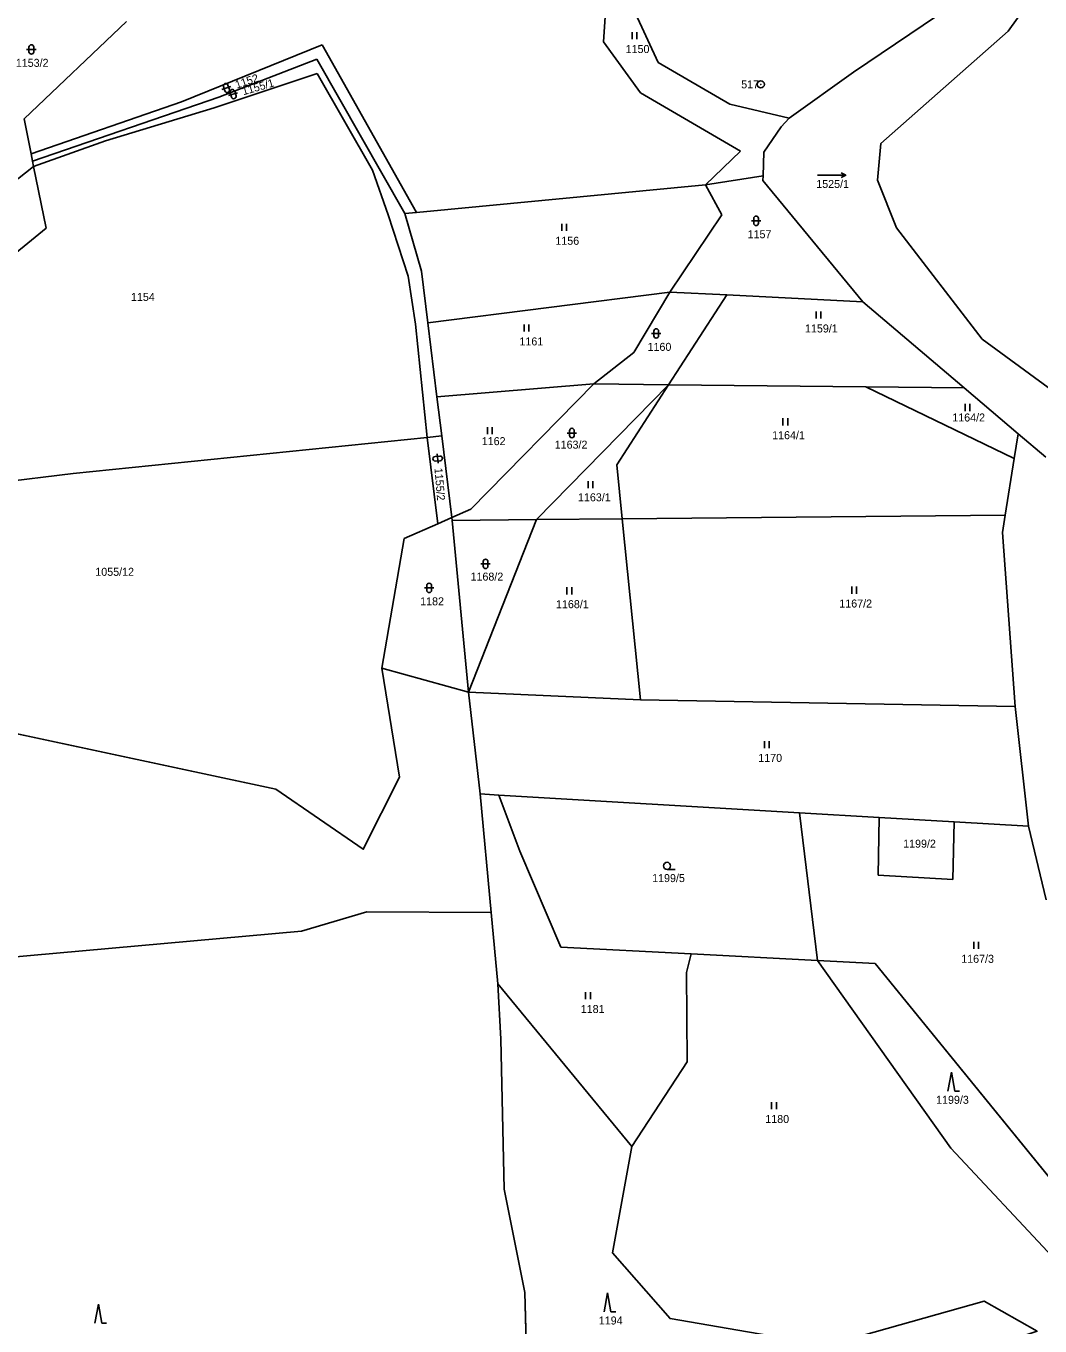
# Model space of a CAD drawing. Extents: x -760642 to -757221, y -1092371 to -1088855.
# Drawn here: x -759256.9 to -759041.5, y -1090879.2 to -1090603 of the extents above; entities that cross this region are included whole.
import ezdxf

# ---------------------------------------------------------------- set-up
doc = ezdxf.new("R2010")
doc.units = 0
for name, color, linetype in [('Vrstva 1', 7, 'Continuous'), ('Vrstva 17', 7, 'Continuous'), ('Vrstva 18', 7, 'Continuous'), ('Vrstva 24', 7, 'Continuous'), ('Vrstva 25', 7, 'Continuous'), ('Vrstva 30', 7, 'Continuous')]:
    doc.layers.add(name, color=color, linetype=linetype)

msp = doc.modelspace()

# ---------------------------------------------------------------- linework, layer by layer
at = {"layer": 'Vrstva 1'}
for p, q in [((-759132.43, -1090577.06), (-759134.2, -1090606.39)), ((-759033.66, -1090583.79), (-759048.27, -1090604.13)), ((-759127.44, -1090600.38), (-759122.61, -1090610.8)), ((-759063.28, -1090600.8), (-759081.11, -1090612.81)), ((-759235.58, -1090602.05), (-759257.35, -1090622.75)), ((-759048.27, -1090604.13), (-759075.3, -1090628.01)), ((-759134.2, -1090606.39), (-759126.37, -1090617.23)), ((-759223.9, -1090619.16), (-759194, -1090607.04)), ((-759194, -1090607.04), (-759173.99, -1090642.62)), ((-759195.13, -1090610.05), (-759215.93, -1090618.11)), ((-759195.13, -1090610.05), (-759176.47, -1090642.86)), ((-759122.61, -1090610.8), (-759107.37, -1090619.62)), ((-759195.07, -1090613.1), (-759216.96, -1090620.43)), ((-759195.07, -1090613.1), (-759183.34, -1090633.62)), ((-759081.11, -1090612.81), (-759094.81, -1090622.6)), ((-759126.37, -1090617.23), (-759105.11, -1090629.6)), ((-759255.84, -1090630.18), (-759223.9, -1090619.16)), ((-759215.93, -1090618.11), (-759255.53, -1090631.72)), ((-759216.96, -1090620.43), (-759240.05, -1090627.39)), ((-759107.37, -1090619.62), (-759094.81, -1090622.6)), ((-759257.35, -1090622.75), (-759255.84, -1090630.18)), ((-759094.81, -1090622.6), (-759096.52, -1090624.45)), ((-759100.18, -1090629.79), (-759096.52, -1090624.45)), ((-759240.05, -1090627.39), (-759255.3, -1090632.86)), ((-759075.3, -1090628.01), (-759076.01, -1090635.76)), ((-759255.84, -1090630.18), (-759255.53, -1090631.72)), ((-759255.53, -1090631.72), (-759255.3, -1090632.86)), ((-759105.11, -1090629.6), (-759112.55, -1090636.79)), ((-759100.34, -1090634.85), (-759100.18, -1090629.79)), ((-759255.3, -1090632.86), (-759274.97, -1090648.39)), ((-759255.3, -1090632.86), (-759252.64, -1090645.98)), ((-759183.34, -1090633.62), (-759180, -1090643.11)), ((-759173.99, -1090642.62), (-759112.55, -1090636.79)), ((-759112.55, -1090636.79), (-759100.34, -1090634.85)), ((-759109.11, -1090643.15), (-759112.55, -1090636.79)), ((-759100.38, -1090635.86), (-759100.34, -1090634.85)), ((-759079.12, -1090661.61), (-759100.38, -1090635.86)), ((-759076.01, -1090635.76), (-759071.96, -1090645.93)), ((-759176.47, -1090642.86), (-759173.99, -1090642.62)), ((-759176.47, -1090642.86), (-759172.92, -1090655.14)), ((-759180, -1090643.11), (-759175.73, -1090656.16)), ((-759109.11, -1090643.15), (-759120.11, -1090659.56)), ((-759269.58, -1090659.81), (-759252.64, -1090645.98)), ((-759071.96, -1090645.93), (-759053.79, -1090669.58)), ((-759175.73, -1090656.16), (-759174.15, -1090666.39)), ((-759172.92, -1090655.14), (-759171.56, -1090666.11)), ((-759171.56, -1090666.11), (-759120.11, -1090659.56)), ((-759120.11, -1090659.56), (-759127.77, -1090672.39)), ((-759108, -1090660.17), (-759120.39, -1090679.27)), ((-759120.11, -1090659.56), (-759108, -1090660.17)), ((-759108, -1090660.17), (-759079.12, -1090661.61)), ((-759057.59, -1090679.92), (-759079.12, -1090661.61)), ((-759174.15, -1090666.39), (-759171.71, -1090690.46)), ((-759171.56, -1090666.11), (-759169.62, -1090681.83)), ((-759053.79, -1090669.58), (-759039.79, -1090679.81)), ((-759127.77, -1090672.39), (-759136.3, -1090679.08)), ((-759169.62, -1090681.83), (-759136.3, -1090679.08)), ((-759136.3, -1090679.08), (-759162.4, -1090705.68)), ((-759148.48, -1090707.91), (-759120.39, -1090679.27)), ((-759136.3, -1090679.08), (-759120.39, -1090679.27)), ((-759120.39, -1090679.27), (-759131.41, -1090696.28)), ((-759120.39, -1090679.27), (-759078.53, -1090679.71)), ((-759078.53, -1090679.71), (-759057.59, -1090679.92)), ((-759078.53, -1090679.71), (-759046.96, -1090694.93)), ((-759046.12, -1090689.67), (-759057.59, -1090679.92)), ((-759169.62, -1090681.83), (-759168.6, -1090690.12)), ((-759046.12, -1090689.67), (-759046.96, -1090694.93)), ((-759040.29, -1090694.63), (-759046.12, -1090689.67)), ((-759246.91, -1090698.11), (-759171.71, -1090690.46)), ((-759171.71, -1090690.46), (-759168.6, -1090690.12)), ((-759171.71, -1090690.46), (-759169.46, -1090708.78)), ((-759168.6, -1090690.12), (-759166.45, -1090707.46)), ((-759046.96, -1090694.93), (-759048.88, -1090706.94)), ((-759316.96, -1090706.48), (-759246.91, -1090698.11)), ((-759131.41, -1090696.28), (-759130.25, -1090707.74)), ((-759162.4, -1090705.68), (-759166.45, -1090707.46)), ((-759169.46, -1090708.78), (-759176.58, -1090711.91)), ((-759166.45, -1090707.46), (-759169.46, -1090708.78)), ((-759166.45, -1090707.46), (-759166.39, -1090708.09)), ((-759166.39, -1090708.09), (-759148.48, -1090707.91)), ((-759166.39, -1090708.09), (-759162.88, -1090744.54)), ((-759148.48, -1090707.91), (-759162.88, -1090744.54)), ((-759148.48, -1090707.91), (-759130.25, -1090707.74)), ((-759130.25, -1090707.74), (-759048.88, -1090706.94)), ((-759130.25, -1090707.74), (-759126.35, -1090746.2)), ((-759048.88, -1090706.94), (-759049.47, -1090710.65)), ((-759176.58, -1090711.91), (-759181.35, -1090739.43)), ((-759049.47, -1090710.65), (-759046.78, -1090747.61)), ((-759181.35, -1090739.43), (-759177.54, -1090762.65)), ((-759181.35, -1090739.43), (-759162.88, -1090744.54)), ((-759126.35, -1090746.2), (-759162.88, -1090744.54)), ((-759160.47, -1090766.2), (-759162.88, -1090744.54)), ((-759046.78, -1090747.61), (-759126.35, -1090746.2)), ((-759046.78, -1090747.61), (-759043.95, -1090773.03)), ((-759203.82, -1090765.18), (-759276.75, -1090749.57)), ((-759177.54, -1090762.65), (-759185.27, -1090777.95)), ((-759185.27, -1090777.95), (-759203.82, -1090765.18)), ((-759160.47, -1090766.2), (-759156.47, -1090766.43)), ((-759158.12, -1090791.4), (-759160.47, -1090766.2)), ((-759156.47, -1090766.43), (-759152, -1090778.35)), ((-759156.47, -1090766.43), (-759092.61, -1090770.18)), ((-759092.61, -1090770.18), (-759075.65, -1090771.17)), ((-759092.61, -1090770.18), (-759088.76, -1090801.57)), ((-759075.85, -1090783.42), (-759075.65, -1090771.17)), ((-759075.65, -1090771.17), (-759059.72, -1090772.1)), ((-759059.72, -1090772.1), (-759060.01, -1090784.36)), ((-759059.72, -1090772.1), (-759043.95, -1090773.03)), ((-759043.95, -1090773.03), (-759040.18, -1090788.67)), ((-759152, -1090778.35), (-759143.31, -1090798.73)), ((-759075.85, -1090783.42), (-759060.01, -1090784.36)), ((-759198.4, -1090795.36), (-759184.51, -1090791.26)), ((-759184.51, -1090791.26), (-759158.12, -1090791.4)), ((-759156.7, -1090806.56), (-759158.12, -1090791.4)), ((-759262.25, -1090801.05), (-759198.4, -1090795.36)), ((-759143.31, -1090798.73), (-759115.6, -1090800.17)), ((-759116.57, -1090804.13), (-759115.6, -1090800.17)), ((-759115.6, -1090800.17), (-759088.76, -1090801.57)), ((-759060.43, -1090841.45), (-759088.76, -1090801.57)), ((-759088.76, -1090801.57), (-759076.48, -1090802.21)), ((-759031.29, -1090857.79), (-759076.48, -1090802.21)), ((-759116.45, -1090823.08), (-759116.57, -1090804.13)), ((-759156.05, -1090818.26), (-759156.7, -1090806.56)), ((-759156.7, -1090806.56), (-759128.18, -1090841.12)), ((-759155.34, -1090850.18), (-759156.05, -1090818.26)), ((-759128.18, -1090841.12), (-759116.45, -1090823.08)), ((-759132.34, -1090863.69), (-759128.18, -1090841.12)), ((-759038.83, -1090864.58), (-759060.43, -1090841.45)), ((-759150.92, -1090872.11), (-759155.34, -1090850.18)), ((-759120.09, -1090877.65), (-759132.34, -1090863.69)), ((-759150.4, -1090892.85), (-759150.92, -1090872.11)), ((-759086.75, -1090883.38), (-759053.39, -1090873.96)), ((-759053.39, -1090873.96), (-759042.11, -1090880.34)), ((-759120.09, -1090877.65), (-759086.75, -1090883.38))]:
    msp.add_line(p, q, dxfattribs=at)
at = {"layer": 'Vrstva 24'}
for radius in [0.75, 0.0327]:
    msp.add_circle((-759100.81, -1090615.41), radius, dxfattribs=at)
at = {"layer": 'Vrstva 25'}
for p, q in [((-759128.167, -1090604.325), (-759128.167, -1090605.825)), ((-759127.145, -1090605.825), (-759127.145, -1090604.325)), ((-759256.79, -1090607.99), (-759254.79, -1090607.99)), ((-759256.29, -1090608.49), (-759256.29, -1090607.49)), ((-759255.29, -1090608.49), (-759255.29, -1090607.49)), ((-759215.285, -1090616.508), (-759213.388, -1090615.875)), ((-759214.652, -1090616.824), (-759214.969, -1090615.875)), ((-759213.704, -1090616.508), (-759214.02, -1090615.559)), ((-759213.879, -1090617.769), (-759211.959, -1090617.211)), ((-759213.26, -1090618.109), (-759213.539, -1090617.149)), ((-759212.299, -1090617.83), (-759212.579, -1090616.87)), ((-759088.76, -1090634.73), (-759082.76, -1090634.73)), ((-759143.117, -1090645.065), (-759143.117, -1090646.565)), ((-759142.095, -1090646.565), (-759142.095, -1090645.065)), ((-759102.8, -1090644.41), (-759100.8, -1090644.41)), ((-759102.3, -1090644.91), (-759102.3, -1090643.91)), ((-759101.3, -1090644.91), (-759101.3, -1090643.91)), ((-759089.077, -1090663.695), (-759089.077, -1090665.195)), ((-759088.055, -1090665.195), (-759088.055, -1090663.695)), ((-759151.097, -1090666.455), (-759151.097, -1090667.955)), ((-759150.075, -1090667.955), (-759150.075, -1090666.455)), ((-759124.03, -1090668.34), (-759122.03, -1090668.34)), ((-759123.53, -1090668.84), (-759123.53, -1090667.84)), ((-759122.53, -1090668.84), (-759122.53, -1090667.84)), ((-759057.397, -1090683.325), (-759057.397, -1090684.825)), ((-759056.375, -1090684.825), (-759056.375, -1090683.325)), ((-759096.107, -1090686.375), (-759096.107, -1090687.875)), ((-759095.085, -1090687.875), (-759095.085, -1090686.375)), ((-759158.887, -1090688.235), (-759158.887, -1090689.735)), ((-759157.865, -1090689.735), (-759157.865, -1090688.235)), ((-759141.95, -1090689.5), (-759139.95, -1090689.5)), ((-759141.45, -1090690), (-759141.45, -1090689)), ((-759140.45, -1090690), (-759140.45, -1090689)), ((-759170.004, -1090694.479), (-759169.008, -1090694.395)), ((-759169.919, -1090695.476), (-759168.923, -1090695.391)), ((-759169.548, -1090693.939), (-759169.379, -1090695.932)), ((-759137.497, -1090699.725), (-759137.497, -1090701.225)), ((-759136.475, -1090701.225), (-759136.475, -1090699.725)), ((-759160.28, -1090717.31), (-759158.28, -1090717.31)), ((-759159.78, -1090717.81), (-759159.78, -1090716.81)), ((-759158.78, -1090717.81), (-759158.78, -1090716.81)), ((-759172.27, -1090722.41), (-759170.27, -1090722.41)), ((-759171.77, -1090722.91), (-759171.77, -1090721.91)), ((-759170.77, -1090722.91), (-759170.77, -1090721.91)), ((-759141.997, -1090722.285), (-759141.997, -1090723.785)), ((-759140.975, -1090723.785), (-759140.975, -1090722.285)), ((-759081.497, -1090722.145), (-759081.497, -1090723.645)), ((-759080.475, -1090723.645), (-759080.475, -1090722.145)), ((-759100.057, -1090754.945), (-759100.057, -1090756.445)), ((-759099.035, -1090756.445), (-759099.035, -1090754.945)), ((-759118.98, -1090782.22), (-759120.73, -1090782.22)), ((-759055.577, -1090797.635), (-759055.577, -1090799.135)), ((-759054.555, -1090799.135), (-759054.555, -1090797.635)), ((-759138.047, -1090808.305), (-759138.047, -1090809.805)), ((-759137.025, -1090809.805), (-759137.025, -1090808.305)), ((-759060.332, -1090825.319), (-759061.065, -1090829.319)), ((-759060.332, -1090825.319), (-759059.599, -1090829.319)), ((-759059.599, -1090829.319), (-759058.599, -1090829.319)), ((-759098.507, -1090831.675), (-759098.507, -1090833.175)), ((-759097.485, -1090833.175), (-759097.485, -1090831.675)), ((-759241.552, -1090874.619), (-759242.285, -1090878.619)), ((-759241.552, -1090874.619), (-759240.819, -1090878.619)), ((-759133.372, -1090872.209), (-759134.105, -1090876.209)), ((-759133.372, -1090872.209), (-759132.639, -1090876.209)), ((-759132.639, -1090876.209), (-759131.639, -1090876.209)), ((-759240.819, -1090878.619), (-759239.819, -1090878.619))]:
    msp.add_line(p, q, dxfattribs=at)
msp.add_lwpolyline([(-759083.76, -1090634.23), (-759082.76, -1090634.73), (-759083.76, -1090635.23)], dxfattribs=at)
msp.add_circle((-759120.73, -1090781.47), 0.75, dxfattribs=at)
for centre, start, end in [((-759255.79, -1090607.49), 0, 180), ((-759255.79, -1090608.49), 180, 0), ((-759214.494, -1090615.717), 18.43488, 198.43488), ((-759214.178, -1090616.666), 198.43488, 18.43488), ((-759213.059, -1090617.01), 16.21341, 196.21341), ((-759212.78, -1090617.97), 196.21341, 16.21341), ((-759101.8, -1090643.91), 0, 180), ((-759101.8, -1090644.91), 180, 0), ((-759123.03, -1090667.84), 0, 180), ((-759123.03, -1090668.84), 180, 0), ((-759140.95, -1090689), 0, 180), ((-759140.95, -1090690), 180, 0), ((-759169.962, -1090694.978), 94.86459, 274.86459), ((-759168.965, -1090694.893), 274.86459, 94.86459), ((-759159.28, -1090716.81), 0, 180), ((-759159.28, -1090717.81), 180, 0), ((-759171.27, -1090721.91), 0, 180), ((-759171.27, -1090722.91), 180, 0)]:
    msp.add_arc(centre, 0.5, start, end, dxfattribs=at)
at = {"layer": 'Vrstva 30'}
for points in [[(-759304.08, -1090757.57), (-759315.07, -1090778.1), (-759330.79, -1090805.66), (-759342.28, -1090802.13), (-759356.77, -1090806.59), (-759359.59, -1090797.7), (-759367.06, -1090816.52), (-759331.64, -1090824.28), (-759307.99, -1090822.79), (-759290.58, -1090809.77), (-759262.25, -1090801.05), (-759198.4, -1090795.36), (-759184.51, -1090791.26), (-759158.12, -1090791.4), (-759160.47, -1090766.2), (-759162.88, -1090744.54), (-759181.35, -1090739.43), (-759177.54, -1090762.65), (-759185.27, -1090777.95), (-759203.82, -1090765.18), (-759276.75, -1090749.57), (-759314.27, -1090749.48), (-759304.08, -1090757.57)], [(-759150.4, -1090892.85), (-759150.92, -1090872.11), (-759155.34, -1090850.18), (-759156.05, -1090818.26), (-759156.7, -1090806.56), (-759158.12, -1090791.4), (-759184.51, -1090791.26), (-759198.4, -1090795.36), (-759262.25, -1090801.05), (-759290.58, -1090809.77), (-759307.99, -1090822.79), (-759331.64, -1090824.28), (-759367.06, -1090816.52), (-759354.85, -1090867.21), (-759354.76, -1090881.48)], [(-759076.48, -1090802.21), (-759088.76, -1090801.57), (-759060.43, -1090841.45), (-759038.83, -1090864.58), (-759031.29, -1090857.79), (-759076.48, -1090802.21)], [(-759156.05, -1090818.26), (-759155.34, -1090850.18), (-759150.92, -1090872.11), (-759150.4, -1090892.85), (-759150.4, -1090893.77), (-759147.8, -1090895.52), (-759143.25, -1090898.24), (-759124.76, -1090896.25), (-759114.86, -1090905.07), (-759104.3, -1090905.41), (-759084.53, -1090892.6), (-759054.59, -1090884.54), (-759042.11, -1090880.34), (-759053.39, -1090873.96), (-759086.75, -1090883.38), (-759120.09, -1090877.65), (-759132.34, -1090863.69), (-759128.18, -1090841.12), (-759156.7, -1090806.56), (-759156.05, -1090818.26)]]:
    msp.add_lwpolyline(points, dxfattribs=at)

# ---------------------------------------------------------------- texts
at = {"layer": 'Vrstva 17'}
msp.add_text('517', height=1.7, dxfattribs=at).set_placement((-759104.98, -1090616.26))
at = {"layer": 'Vrstva 18'}
for s, p in [('1150', (-759129.53, -1090608.76)), ('1153/2', (-759259.09, -1090611.69)), ('1525/1', (-759089.031, -1090637.43)), ('1156', (-759144.46, -1090649.5)), ('1157', (-759103.62, -1090648.11)), ('1154', (-759234.62, -1090661.44)), ('1159/1', (-759091.42, -1090668.13)), ('1161', (-759152.09, -1090670.89)), ('1160', (-759124.87, -1090672.04)), ('1164/2', (-759060.13, -1090687.05)), ('1164/1', (-759098.4, -1090690.81)), ('1162', (-759160.1, -1090692.08)), ('1163/2', (-759144.6, -1090692.82)), ('1163/1', (-759139.65, -1090704.01)), ('1055/12', (-759242.2, -1090719.84)), ('1168/2', (-759162.48, -1090720.86)), ('1182', (-759173.18, -1090726.11)), ('1168/1', (-759144.32, -1090726.72)), ('1167/2', (-759084.13, -1090726.58)), ('1170', (-759101.35, -1090759.38)), ('1199/2', (-759070.568, -1090777.61)), ('1199/5', (-759123.894, -1090784.92)), ('1167/3', (-759058.23, -1090802.07)), ('1181', (-759139.064, -1090812.74)), ('1199/3', (-759063.57, -1090832.03)), ('1180', (-759099.856, -1090836.11)), ('1194', (-759135.23, -1090878.92))]:
    msp.add_text(s, height=1.7, dxfattribs=at).set_placement(p)
for s, rotation, p in [('1152', 18.43497, (-759212.15, -1090616.35)), ('1155/1', 16.21341, (-759210.74, -1090617.75)), ('1155/2', 274.8645, (-759170.15, -1090696.99))]:
    msp.add_text(s, height=1.7, rotation=rotation, dxfattribs=at).set_placement(p)

doc.saveas('drawing.dxf')
